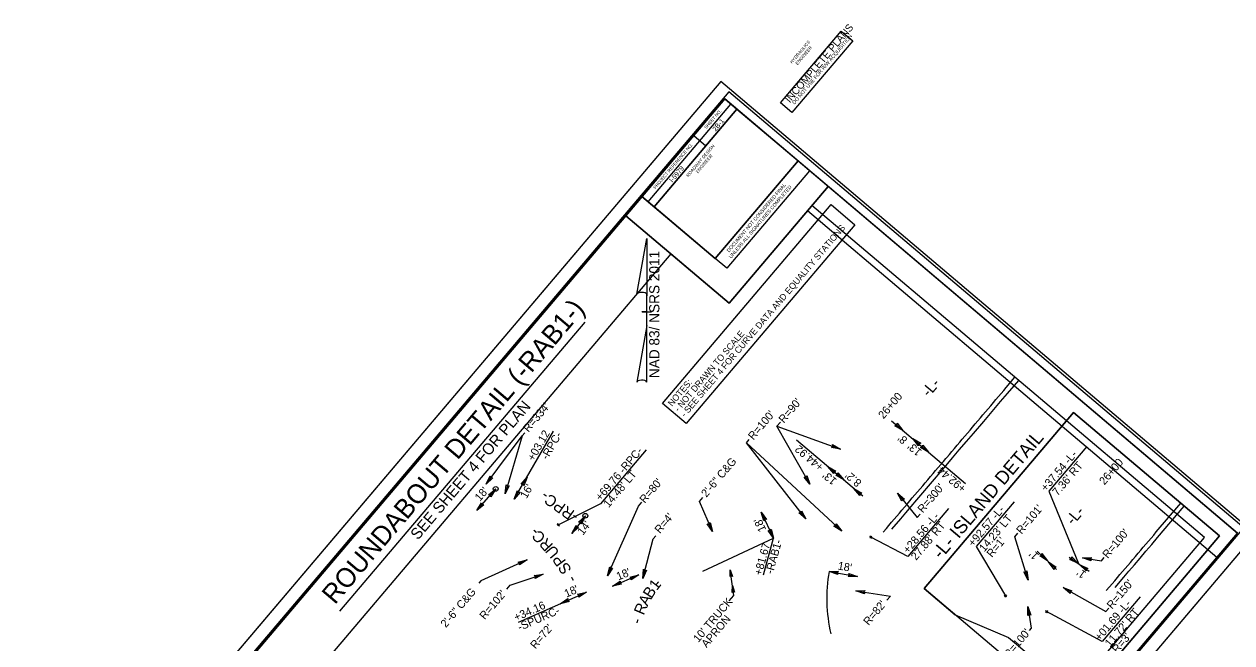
# Model space of a CAD drawing. Extents: x 1761753 to 1762923, y 422186 to 423380.
# Drawn here: x 1761775 to 1762529, y 422993 to 423380 of the extents above; entities that cross this region are included whole.
import ezdxf

# ---------------------------------------------------------------- set-up
doc = ezdxf.new("R2010")
doc.units = 0
for name, color, linetype in [('Default', 7, 'Continuous'), ('Matchline', 7, 'Continuous'), ('Old_Level_11', 7, 'Continuous'), ('Old_Level_2', 7, 'Continuous'), ('Prop Conc 2ft 6in Curb and Gutter', 7, 'Continuous'), ('Prop Conc 5in Monolithic Keyed In Island', 7, 'Continuous'), ('Prop Dimension Text', 7, 'Continuous'), ('Prop Grid Mask', 7, 'Continuous'), ('Prop Horizontal Alignment Station Label', 7, 'Continuous'), ('Prop Lane Lines', 7, 'Continuous'), ('Prop RDY Traffic Signal CELL', 7, 'Continuous'), ('Prop Shade Light', 7, 'Continuous'), ('Sheet Cutting Line CELL', 7, 'Continuous'), ('Sheet Data Field CELL', 7, 'Continuous'), ('Sheet North Arrow CELL', 7, 'Continuous'), ('Sheet Plan CELL', 7, 'Continuous'), ('Sheet Plan Layout CELL', 7, 'Continuous'), ('Sheet Plot Border Inside CELL', 7, 'Continuous'), ('Sheet Plot Border Outside CELL', 7, 'Continuous'), ('Sheet Symbology CELL', 7, 'Continuous')]:
    doc.layers.add(name, color=color, linetype=linetype)

# ---------------------------------------------------------------- blocks, each defined once
blk = doc.blocks.new('Terminator')
at = {"layer": 'Sheet Data Field CELL'}
blk.add_lwpolyline([(-9, 1.55), (0, 0), (-9.05, -1.6), (-7.9, 0)], close=True, dxfattribs=at)

msp = doc.modelspace()

# ---------------------------------------------------------------- linework, layer by layer
at = {"layer": 'Default'}
for p, q in [((1762108.48, 423066.91), (1762107.9, 423067.4)), ((1762109.32, 423066.21), (1762108.48, 423066.91)), ((1762303.72, 423059.17), (1762303.14, 423059.66)), ((1762304.55, 423058.47), (1762303.72, 423059.17)), ((1762387.8, 423022.41), (1762387.22, 423022.9)), ((1762388.63, 423021.71), (1762387.8, 423022.41)), ((1762413.5, 423012.6), (1762412.91, 423013.09)), ((1762414.33, 423011.9), (1762413.5, 423012.6))]:
    msp.add_line(p, q, dxfattribs=at)
at = {"layer": 'Matchline'}
for p, q in [((1762157.61, 423211.03), (1762163.76, 423245.8)), ((1762163.79, 423245.8), (1762163.76, 423245.8)), ((1762163.79, 423245.8), (1762163.76, 423245.8)), ((1762163.79, 423245.8), (1762163.79, 423209.95)), ((1762163.79, 423191.35), (1762163.79, 423211)), ((1762163.79, 423209.95), (1762163.79, 423210.96)), ((1762160.79, 423200.05), (1762160.76, 423200.05)), ((1762163.46, 423200.05), (1762160.79, 423200.05)), ((1762160.83, 423200.05), (1762166.83, 423200.05)), ((1762163.79, 423191.35), (1762157.53, 423155.91)), ((1762163.83, 423156.06), (1762163.79, 423191.35))]:
    msp.add_line(p, q, dxfattribs=at)
for centre, start_param, end_param in [((1762160.71, 423210.66), 0.216388, 2.908219), ((1762160.71, 423155.78), 0.201328, 3.141593)]:
    msp.add_ellipse(centre, major_axis=(3.17, -0.02), ratio=0.461098, start_param=start_param, end_param=end_param, dxfattribs=at)
at = {"layer": 'Old_Level_2'}
msp.add_lwpolyline([(1762254.44, 423324.55), (1762247.26, 423330.63), (1762285.27, 423375.49), (1762292.44, 423369.42)], close=True, dxfattribs=at)
at = {"layer": 'Prop Conc 2ft 6in Curb and Gutter'}
msp.add_lwpolyline([(1762106.21, 422556.31), (1762536.95, 423064.78), (1762214.97, 423337.56), (1761784.22, 422829.09)], close=True, dxfattribs=at)
at = {"layer": 'Prop Conc 5in Monolithic Keyed In Island'}
msp.add_line((1761971.96, 423012.67), (1762125.24, 423193.6), dxfattribs=at)
msp.add_lwpolyline([(1762337.14, 423026.87), (1762430.51, 423137.08), (1762521.72, 423059.81), (1762428.35, 422949.6)], close=True, dxfattribs=at)
at = {"layer": 'Prop Dimension Text'}
for p, q in [((1762210.03, 423344.1), (1761774.75, 422830.29)), ((1762108.95, 422547.17), (1762544.23, 423060.98))]:
    msp.add_line(p, q, dxfattribs=at)
at = {"layer": 'Prop Grid Mask'}
for p, q in [((1762164.6, 423268.8), (1762216.33, 423329.85)), ((1762168.43, 423265.56), (1762220.14, 423326.62)), ((1762223.96, 423323.39), (1762258.3, 423294.3)), ((1762193.12, 423310.18), (1762200.76, 423303.73)), ((1762168.43, 423265.56), (1762172.24, 423262.33))]:
    msp.add_line(p, q, dxfattribs=at)
for points in [[(1762212.5, 423333.11), (1761824.66, 422875.29), (1762145.13, 422603.81), (1762532.96, 423061.62)], [(1762160.77, 423272.05), (1762212.5, 423333.11), (1762220.14, 423326.62), (1762168.43, 423265.56)], [(1762168.43, 423265.56), (1762220.15, 423326.62), (1762258.29, 423294.3), (1762206.57, 423233.25)], [(1762145.13, 422603.81), (1761824.66, 422875.28), (1762160.77, 423272.05), (1762206.57, 423233.25), (1762258.3, 423294.3), (1762532.96, 423061.62)]]:
    msp.add_lwpolyline(points, close=True, dxfattribs=at)
at = {"layer": 'Prop Horizontal Alignment Station Label'}
for points in [[(1762146.91, 422627.42), (1762512.32, 423058.75), (1762267, 423266.56), (1762215.18, 423205.39), (1762178.84, 423236.18), (1761865.25, 422866.02)], [(1762356.54, 423010.43), (1762389.75, 422996.33), (1762421.46, 422969.87), (1762420.74, 422956.05), (1762428.35, 422949.6), (1762521.72, 423059.81), (1762430.51, 423137.08), (1762337.14, 423026.87)]]:
    msp.add_lwpolyline(points, close=True, dxfattribs=at)
at = {"layer": 'Prop Lane Lines'}
msp.add_line((1762198.88, 423037.72), (1762243.01, 423058.43), dxfattribs=at)
msp.add_arc((1762376.27, 423020.6), 100, 170.25355, 192.68582, dxfattribs=at)
at = {"layer": 'Prop RDY Traffic Signal CELL'}
for points in [[(1762215.18, 423205.39), (1762277.05, 423278.42), (1762212.51, 423333.11), (1762150.64, 423260.08)], [(1761824.66, 422875.28), (1762145.13, 422603.81), (1762532.96, 423061.61), (1762277.04, 423278.41), (1762215.18, 423205.39), (1762150.64, 423260.08)]]:
    msp.add_lwpolyline(points, close=True, dxfattribs=at)
at = {"layer": 'Prop Shade Light'}
for p, q in [((1762206.57, 423233.25), (1762258.29, 423294.3)), ((1762206.57, 423233.25), (1762258.29, 423294.3)), ((1762258.3, 423294.3), (1762265.47, 423288.22)), ((1762258.3, 423294.3), (1762265.47, 423288.22)), ((1762265.47, 423288.23), (1762213.75, 423227.17)), ((1762265.47, 423288.23), (1762213.75, 423227.17)), ((1762213.75, 423227.17), (1762206.57, 423233.25)), ((1762213.75, 423227.17), (1762206.57, 423233.25))]:
    msp.add_line(p, q, dxfattribs=at)
at = {"layer": 'Sheet Cutting Line CELL'}
for points in [[(1762316.98, 423064.07), (1762322.48, 423070.52), (1762325.62, 423074.22), (1762328.98, 423078.17), (1762332.54, 423082.38), (1762336.21, 423086.71), (1762339.85, 423091.02), (1762343.48, 423095.3), (1762347.08, 423099.56), (1762350.81, 423103.95), (1762354.8, 423108.65), (1762359.07, 423113.64), (1762363.6, 423118.93), (1762367.91, 423123.95), (1762374.31, 423131.46), (1762378.51, 423136.42), (1762384.89, 423143.86), (1762389.17, 423148.83), (1762396.26, 423157.06)], [(1762456.46, 423027.55), (1762461.96, 423034.01), (1762465.1, 423037.7), (1762468.45, 423041.65), (1762472.02, 423045.86), (1762475.68, 423050.19), (1762479.33, 423054.5), (1762482.95, 423058.78), (1762499.65, 423078.51)]]:
    msp.add_lwpolyline(points, dxfattribs=at)
at = {"layer": 'Sheet Data Field CELL'}
for points in [[(1762320.17, 423130.24), (1762323.87, 423125.83), (1762318.87, 423128.74), (1762320.07, 423129.04)], [(1762296.84, 423085.15), (1762293.15, 423089.56), (1762298.15, 423086.65), (1762296.94, 423086.35)], [(1762282.15, 423067.44), (1762285.64, 423062.87), (1762280.77, 423066.01), (1762281.99, 423066.25)], [(1762418.3, 423038.89), (1762414.87, 423043.52), (1762419.69, 423040.31), (1762418.47, 423040.08)], [(1762429.33, 423046.63), (1762433.39, 423042.55), (1762428.16, 423045.03), (1762429.33, 423045.44)], [(1762215.81, 423034.36), (1762215.96, 423038.63), (1762217.27, 423034.53), (1762216.46, 423034.97)]]:
    msp.add_lwpolyline(points, close=True, dxfattribs=at)
at = {"layer": 'Sheet North Arrow CELL'}
msp.add_lwpolyline([(1762108.95, 422547.17), (1762544.23, 423060.98), (1762210.03, 423344.1), (1761774.75, 422830.29)], close=True, dxfattribs=at)
at = {"layer": 'Sheet Plan CELL'}
for p, q in [((1762080.97, 423082.81), (1762105.61, 423125.35)), ((1762245.13, 423128.43), (1762284.88, 423114.15)), ((1762316.77, 423131.84), (1762362.99, 423092.68)), ((1762085.95, 423122.32), (1762075.22, 423086.06)), ((1762263.19, 423070.43), (1762226.12, 423118.05)), ((1762257.43, 423119.82), (1762298.79, 423084.79)), ((1762057.59, 423075.62), (1762069.4, 423089.2)), ((1762125.41, 423072.41), (1762116.93, 423061.26)), ((1762235.36, 423074.72), (1762243.01, 423058.43)), ((1762107.9, 423067.4), (1762109.32, 423066.21)), ((1762109.15, 423067.44), (1762108, 423066.09)), ((1762236.68, 423035.44), (1762243.01, 423058.43)), ((1762303.14, 423059.66), (1762304.55, 423058.47)), ((1762304.39, 423059.7), (1762303.24, 423058.35)), ((1762419.87, 423038.74), (1762407.73, 423050.35)), ((1762427.7, 423046.6), (1762440.15, 423037.76)), ((1762142.32, 423028.45), (1762158.93, 423035.4)), ((1762277.71, 423037.52), (1762295.45, 423034.48)), ((1762083.58, 423005.94), (1762126.14, 423024.7)), ((1762387.22, 423022.9), (1762388.63, 423021.71)), ((1762388.47, 423022.94), (1762387.32, 423021.59)), ((1762412.91, 423013.09), (1762414.33, 423011.9)), ((1762414.16, 423013.13), (1762413.02, 423011.78))]:
    msp.add_line(p, q, dxfattribs=at)
msp.add_lwpolyline([(1762173.58, 423142.61), (1762278.98, 423267.02), (1762293.83, 423254.43), (1762188.44, 423130.02)], close=True, dxfattribs=at)
for points in [[(1762265.74, 423092.15), (1762245.13, 423128.43), (1762247.34, 423131.04)], [(1762063.42, 423092.28), (1762085.95, 423122.32), (1762087.61, 423124.29)], [(1762285.64, 423062.87), (1762226.12, 423118.05), (1762227.78, 423120.02)], [(1762163.46, 423113.6), (1762134.9, 423079.88), (1762108.61, 423066.8)], [(1762438.71, 423115.65), (1762415.07, 423087.75), (1762433.47, 423042.66)], [(1762139.26, 423034.94), (1762158.59, 423078.49), (1762160.73, 423081.02)], [(1762204.8, 423062.59), (1762196.66, 423081.24), (1762198.87, 423083.85)], [(1762320.44, 423086.62), (1762332.77, 423071.32), (1762334.59, 423073.47)], [(1762393.3, 423081.08), (1762369.67, 423053.19), (1762387.93, 423022.31)], [(1762352.38, 423076.88), (1762327.01, 423046.93), (1762303.85, 423059.06)], [(1762161.32, 423033.16), (1762167.69, 423057.95), (1762169.35, 423059.92)], [(1762402.04, 423032.19), (1762393.78, 423059.31), (1762395.6, 423061.46)], [(1762089.09, 423044.9), (1762060.11, 423031.75), (1762058.87, 423030.29)], [(1762435.99, 423046.05), (1762447.85, 423044.22), (1762449.67, 423046.37)], [(1762076.4, 423026.59), (1762078.42, 423028.98), (1762099.1, 423035.92)], [(1762215.31, 423019.19), (1762218.15, 423022.54), (1762215.96, 423038.63)], [(1762423.97, 423027.47), (1762450.59, 423012.49), (1762452.41, 423014.64)], [(1762294.41, 423025.52), (1762315.98, 423022.13), (1762313.78, 423019.53)], [(1762472.02, 423021.7), (1762448.38, 422993.8), (1762413.62, 423012.49)], [(1762401.84, 423015.7), (1762404.05, 423002.16), (1762402.81, 423000.7)]]:
    msp.add_lwpolyline(points, dxfattribs=at)
at = {"layer": 'Sheet Plan Layout CELL'}
for points in [[(1762311.46, 423062.1), (1762313.51, 423064.51), (1762315.13, 423066.42), (1762316.75, 423068.32), (1762318.37, 423070.23), (1762319.99, 423072.13), (1762321.61, 423074.04), (1762323.23, 423075.94), (1762324.85, 423077.85), (1762326.47, 423079.75), (1762328.09, 423081.66), (1762329.71, 423083.56), (1762331.32, 423085.47), (1762332.94, 423087.37), (1762334.56, 423089.27), (1762336.18, 423091.18), (1762337.8, 423093.08), (1762339.42, 423094.99), (1762341.04, 423096.89), (1762342.66, 423098.8), (1762344.28, 423100.7), (1762345.9, 423102.61), (1762347.52, 423104.51), (1762349.13, 423106.42), (1762350.75, 423108.32), (1762351.22, 423108.87), (1762352.84, 423110.78), (1762354.46, 423112.68), (1762356.07, 423114.59), (1762357.69, 423116.49), (1762359.31, 423118.4), (1762360.93, 423120.3), (1762362.54, 423122.21), (1762364.16, 423124.12), (1762365.78, 423126.02), (1762367.4, 423127.93), (1762369.01, 423129.83), (1762370.63, 423131.74), (1762372.25, 423133.65), (1762373.87, 423135.55), (1762375.48, 423137.46), (1762377.1, 423139.36), (1762378.72, 423141.27), (1762380.34, 423143.18), (1762381.95, 423145.08), (1762383.57, 423146.99), (1762385.19, 423148.89), (1762386.81, 423150.8), (1762388.43, 423152.71), (1762393.85, 423159.1)], [(1762450.93, 423025.58), (1762452.99, 423028), (1762454.61, 423029.9), (1762456.23, 423031.81), (1762457.85, 423033.71), (1762459.47, 423035.62), (1762461.09, 423037.52), (1762462.71, 423039.42), (1762464.32, 423041.33), (1762465.94, 423043.23), (1762467.56, 423045.14), (1762469.18, 423047.04), (1762470.8, 423048.95), (1762472.42, 423050.85), (1762474.04, 423052.76), (1762475.66, 423054.66), (1762477.28, 423056.57), (1762478.9, 423058.47), (1762480.52, 423060.38), (1762482.13, 423062.28), (1762497.49, 423080.34)]]:
    msp.add_lwpolyline(points, dxfattribs=at)
at = {"layer": 'Sheet Plot Border Inside CELL'}
for centre in [(1762069.4, 423089.2), (1762125.41, 423072.41)]:
    msp.add_circle(centre, 1.5, dxfattribs=at)
at = {"layer": 'Sheet Symbology CELL'}
msp.add_lwpolyline([(1762158.05, 422619.07), (1762520.03, 423046.36), (1762264.12, 423263.16), (1762215.18, 423205.39), (1762150.64, 423260.08), (1761837.59, 422890.55)], close=True, dxfattribs=at)

# ---------------------------------------------------------------- block references
at = {"layer": 'Default'}
for p, xscale, yscale, rotation in [((1762329.97, 423120.66), 0.6300000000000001, 0.6299999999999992, 139.73010343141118), ((1762284.88, 423114.15), 0.6300000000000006, 0.629999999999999, -19.763003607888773), ((1762339.89, 423112.25), 0.6300000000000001, 0.6299999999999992, -40.269896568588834), ((1762276.97, 423103.27), 0.6300000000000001, 0.6299999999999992, 139.73010343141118), ((1762063.42, 423092.28), 0.6300000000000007, 0.6299999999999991, -126.87233818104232), ((1762088.99, 423096.65), 0.6300000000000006, 0.6299999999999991, 59.92752899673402), ((1762265.74, 423092.15), 0.6300000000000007, 0.629999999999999, -60.4056335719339), ((1762286.89, 423094.86), 0.6300000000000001, 0.6299999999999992, -40.269896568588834), ((1762069.4, 423089.2), 0.6300000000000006, 0.6299999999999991, 48.96093695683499), ((1762075.22, 423086.06), 0.6300000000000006, 0.629999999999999, -106.4878119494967), ((1762080.97, 423082.81), 0.6300000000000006, 0.6299999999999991, -120.07247100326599), ((1762057.59, 423075.62), 0.6300000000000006, 0.6299999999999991, -131.03906304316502), ((1762320.44, 423086.62), 0.6299999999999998, 0.6299999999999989, 128.86226778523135), ((1762125.41, 423072.41), 0.6300000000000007, 0.6299999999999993, 52.76088565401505), ((1762235.36, 423074.72), 0.6300000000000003, 0.6299999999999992, 115.14259082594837), ((1762263.19, 423070.43), 0.6300000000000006, 0.629999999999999, -52.09958711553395), ((1762116.93, 423061.26), 0.6300000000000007, 0.6299999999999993, -127.23911434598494), ((1762204.8, 423062.59), 0.6300000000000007, 0.629999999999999, -66.41357862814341), ((1762243.01, 423058.43), 0.6300000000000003, 0.6299999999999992, -64.85740917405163), ((1762089.09, 423044.9), 0.6300000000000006, 0.6299999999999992, 24.40503624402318), ((1762414.15, 423044.21), 0.630000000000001, 0.6299999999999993, -43.71674051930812), ((1762434.21, 423041.98), 0.6300000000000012, 0.6299999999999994, 144.6215333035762), ((1762435.99, 423046.05), 0.6299999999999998, 0.6299999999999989, 171.23978433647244), ((1762099.1, 423035.92), 0.6300000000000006, 0.629999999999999, 18.53636814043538), ((1762139.26, 423034.94), 0.6300000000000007, 0.629999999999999, -113.93055105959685), ((1762158.93, 423035.4), 0.6300000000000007, 0.6299999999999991, 22.7053564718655), ((1762161.32, 423033.16), 0.6300000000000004, 0.629999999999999, -104.42086929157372), ((1762277.71, 423037.52), 0.6300000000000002, 0.6299999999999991, 170.2535471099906), ((1762295.45, 423034.48), 0.6300000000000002, 0.6299999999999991, -9.74645289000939), ((1762402.04, 423032.19), 0.6300000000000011, 0.6299999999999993, -73.06920236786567), ((1762142.32, 423028.45), 0.6300000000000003, 0.6299999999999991, -157.2946435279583), ((1762423.97, 423027.47), 0.63, 0.629999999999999, 150.637756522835), ((1762109.67, 423017.44), 0.6300000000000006, 0.6299999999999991, -156.21437648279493), ((1762126.14, 423024.7), 0.6300000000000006, 0.6299999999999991, 23.78562351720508), ((1762294.41, 423025.52), 0.6300000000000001, 0.629999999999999, 171.05740195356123), ((1762401.84, 423015.7), 0.6299999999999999, 0.629999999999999, 99.26533092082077)]:
    msp.add_blockref('Terminator', p, dxfattribs=dict(at, xscale=xscale, yscale=yscale, rotation=rotation))
at = {"layer": 'Sheet Plan CELL', "xscale": 0.4687697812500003, "yscale": 0.4687697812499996, "rotation": 97.74339555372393}
msp.add_blockref('Terminator', (1762217.3, 423028.73), dxfattribs=at)

# ---------------------------------------------------------------- texts
at = {"layer": 'Matchline'}
msp.add_text('NAD 83/ NSRS 2011', height=6.375, rotation=90, dxfattribs=at).set_placement((1762171.68, 423158.49))
at = {"layer": 'Old_Level_11'}
for s, p in [('2B-1', (1762206.77, 423312.57)), ('I-5979', (1762179.77, 423280.66))]:
    msp.add_text(s, height=3, rotation=49.73011, dxfattribs=at).set_placement(p)
at = {"layer": 'Old_Level_2'}
for s, height, p in [('INCOMPLETE PLANS', 4.608, (1762253.18, 423330.31)), ('DO NOT USE FOR R/W ACQUISITION', 2.304, (1762256.14, 423329.5))]:
    msp.add_text(s, height=height, rotation=49.7301, dxfattribs=at).set_placement(p)
at = {"layer": 'Prop Dimension Text'}
for s, height, rotation, p in [('ROUNDABOUT DETAIL (-RAB1-)', 12, 49.7301, (1761968.9, 423016.37)), ('SEE SHEET 4 FOR PLAN', 7, 49.7301, (1762020.79, 423056.85)), ("R=334'", 5, 49.7301, (1762089.86, 423124.3)), ("R=90'", 5, 49.7301, (1762249.48, 423129.97)), ("R=100'", 5, 49.7301, (1762230.4, 423119.44)), ('+03.12', 5, 59.92753, (1762093.14, 423106.24)), ('-RPC-', 5, 59.92753, (1762101.68, 423107.08)), ("8'", 5, 139.7301, (1762327.08, 423120.51)), ('-L- ISLAND DETAIL', 8.4, 49.7301, (1762347.74, 423044.78)), ('+69.76 -RPC-', 5, 49.7301, (1762134.97, 423081.39)), ('+44.92', 5, 139.7301, (1762274.76, 423103.71)), ("13'", 5, 139.7301, (1762336.08, 423113.03)), ('+37.54 -L-', 5, 49.7301, (1762413.22, 423087.26)), ('2\'-6" C&G', 5, 49.7301, (1762201.06, 423083.63)), ('+92.44', 5, 139.7301, (1762363.74, 423090.28)), ("7.36' RT", 5, 49.7301, (1762420.48, 423084.5)), ("14.48' LT", 5, 49.7301, (1762139.97, 423077.15)), ("R=80'", 5, 49.7301, (1762162.57, 423079.85)), ("13'", 5, 139.7301, (1762282.97, 423094.91)), ("8.2'", 5, 139.7301, (1762298.45, 423093.74)), ("18'", 5, 48.96094, (1762059.52, 423081.11)), ("16'", 5, 59.92753, (1762088.64, 423082.76)), ("R=300'", 5, 49.7301, (1762336.3, 423073.8)), ("R=4'", 5, 49.7301, (1762171.98, 423060.96)), ('+28.56 -L-', 5, 49.7301, (1762327.09, 423048.43)), ('+92.57 -L-', 5, 49.7301, (1762367.82, 423052.69)), ("14.23' LT", 5, 49.7301, (1762374.68, 423049.48)), ("R=101'", 5, 49.7301, (1762397.98, 423060.54)), ("14'", 5, 52.76089, (1762123.89, 423059.88)), ("18'", 5, 115.14259, (1762238.52, 423063.72)), ("27.88' RT", 5, 49.7301, (1762332.09, 423044.2)), ("R=1'", 5, 49.7301, (1762379.47, 423045.97)), ("R=100'", 5, 49.7301, (1762451.77, 423045.43)), ('+81.67', 5, 74.60679, (1762235.51, 423034.72)), ('-RAB1-', 5, 74.60679, (1762242.6, 423035.65)), ("1'", 5, 136.28326, (1762409.18, 423047.85)), ("18'", 5, 350.25355, (1762282.88, 423038.86)), ("18'", 5, 22.70536, (1762146.05, 423031.93)), ("1'", 5, 144.62153, (1762438.79, 423036.8)), ('2\'-6" C&G', 5, 49.7301, (1762038.27, 423002.07)), ("18'", 5, 23.78562, (1762113.59, 423021.18)), ("R=150'", 5, 49.7301, (1762454.51, 423013.7)), ("R=102'", 5, 49.7301, (1762062.58, 423007.09)), ("10' TRUCK", 5, 49.7301, (1762196.03, 422992.85)), ("R=82'", 5, 49.7301, (1762302.41, 423003.47)), ('+34.16', 5, 23.78562, (1762082.1, 423006.35)), ('-SPURC-', 5, 23.78562, (1762084.42, 423000.22)), ('+01.69 -L-', 5, 49.7301, (1762446.92, 422993.77)), ("11.72' RT", 5, 49.7301, (1762453.28, 422989.96)), ("R=72'", 5, 49.7301, (1762094.28, 422988.75)), ('APRON', 5, 49.7301, (1762201.2, 422989.53)), ("R=100'", 5, 49.7301, (1762390.19, 422982.99)), ("R=3'", 5, 49.7301, (1762457.8, 422986.13))]:
    msp.add_text(s, height=height, rotation=rotation, dxfattribs=at).set_placement(p)
at = {"layer": 'Prop Grid Mask'}
for s, p in [('HYDRAULICS', (1762254.58, 423355.03)), ('ENGINEER', (1762257.99, 423354.12)), ('SHEET NO.', (1762201.05, 423314.13)), ('PROJECT REFERENCE NO.', (1762169.17, 423276.57)), ('ROADWAY DESIGN', (1762189.76, 423284.06)), ('ENGINEER', (1762195.77, 423286.49))]:
    msp.add_text(s, height=2, rotation=49.73011, dxfattribs=at).set_placement(p)
at = {"layer": 'Prop Shade Light'}
for s, p in [('DOCUMENT NOT CONSIDERED FINAL', (1762215.18, 423237.01)), ('DOCUMENT NOT CONSIDERED FINAL', (1762215.18, 423237.01)), ('UNLESS ALL SIGNATURES COMPLETED', (1762216.55, 423233.18)), ('UNLESS ALL SIGNATURES COMPLETED', (1762216.55, 423233.18))]:
    msp.add_text(s, height=2.2, rotation=49.7301, dxfattribs=at).set_placement(p)
at = {"layer": 'Sheet Plan CELL'}
for s, p in [('- SEE SHEET 4 FOR CURVE DATA AND EQUALITY STATIONS', (1762187.61, 423133.73)), ('- NOT DRAWN TO SCALE', (1762183.61, 423137.12)), ('NOTES:', (1762179.61, 423140.51))]:
    msp.add_text(s, height=4, rotation=49.7301, dxfattribs=at).set_placement(p)
at = {"layer": 'Sheet Plot Border Outside CELL'}
for s, height, rotation, p in [('-L-', 7, 49.7301, (1762340.11, 423146.24)), ('26+00', 5, 49.7301, (1762311.73, 423132.6)), ('26+00', 5, 49.7301, (1762449.77, 423091.31)), ('-RPC-', 7, 144.5689, (1762121.76, 423073.3)), ('-L-', 7, 49.7301, (1762430.27, 423066.12)), ('C', 7, 133.31872, (1762101.11, 423059.12)), ('-', 7, 133.31872, (1762097.11, 423063.37)), ('R', 7, 132.70396, (1762105.7, 423054.2)), ('U', 7, 129.7208, (1762109.63, 423049.45)), ('P', 7, 126.46997, (1762113.63, 423044.04)), ('S', 7, 123.38024, (1762117.15, 423038.7)), ('-', 7, 120.18394, (1762120.47, 423032.98)), ('B', 7, 57.17612, (1762166.71, 423020.15)), ('1', 7, 52.03871, (1762170, 423025.29)), ('-', 7, 49.93348, (1762171.47, 423027.31)), ('A', 7, 61.6392, (1762164.23, 423015.46)), ('R', 7, 66.77661, (1762161.85, 423009.84)), ('-', 7, 71.82785, (1762160, 423004.13))]:
    msp.add_text(s, height=height, rotation=rotation, dxfattribs=at).set_placement(p)

doc.saveas('drawing.dxf')
